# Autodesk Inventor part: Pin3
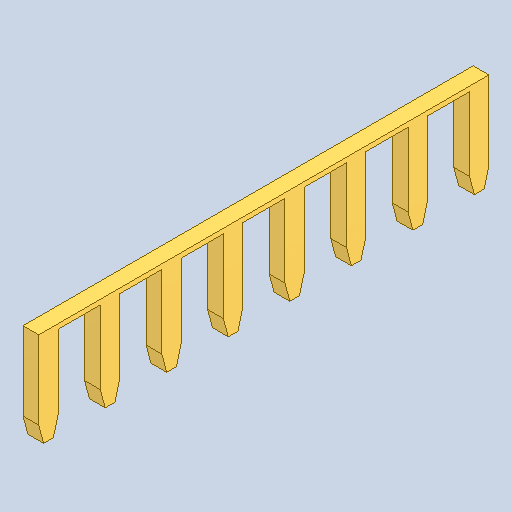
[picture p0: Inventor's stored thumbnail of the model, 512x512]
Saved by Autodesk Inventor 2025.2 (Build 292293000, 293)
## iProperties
Created: 2025-04
Part Number: Pin3
Material: Generic
Description: PART--DESC
Document SubType Name: Modeling
Designer: BennF
Density: 1 g/cm^3
Appearance: Default
Author: BennF
Revision Number: NONE
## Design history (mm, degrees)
feature "Solid13"
body "Solid1"
